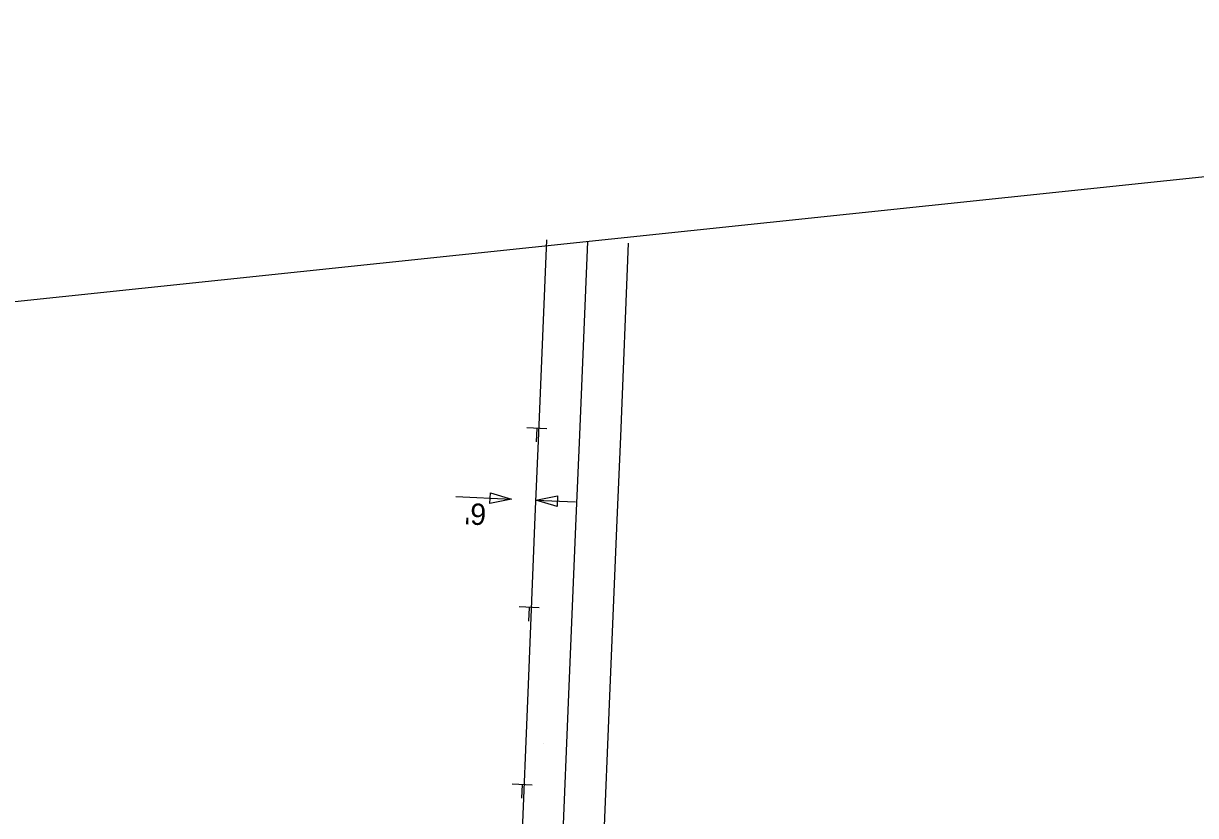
# Model space of a CAD drawing. Extents: x 633427 to 634998, y 288285 to 294065.
# Drawn here: x 634090.7 to 634419.6, y 289761.5 to 289983.8 of the extents above; entities that cross this region are included whole.
import ezdxf

# ---------------------------------------------------------------- set-up
doc = ezdxf.new("R2010")
doc.units = 0
for name, color, linetype in [('59', 7, 'Continuous'), ('Default', 7, 'Continuous'), ('R_Vert Alg Annot', 7, 'Continuous'), ('S_BASELINE', 7, 'Continuous'), ('S_SECONDARY_CTL', 7, 'Continuous'), ('S_WATER_UTILITIES', 7, 'Continuous')]:
    doc.layers.add(name, color=color, linetype=linetype)

msp = doc.modelspace()

# ---------------------------------------------------------------- linework, layer by layer
at = {"layer": '59'}
for p, q in [((634231.96, 289870.43), (634237.58, 289870.16)), ((634234.75, 289870.21), (634234.57, 289866.38)), ((634229.82, 289820.14), (634235.44, 289819.87)), ((634232.61, 289819.92), (634232.43, 289816.09)), ((634227.88, 289770.39), (634233.5, 289770.12)), ((634230.67, 289770.18), (634230.49, 289766.34))]:
    msp.add_line(p, q, dxfattribs=at)
at = {"layer": 'Default'}
for p, q in [((634212.04, 289851.04), (634227.69, 289850.33)), ((634234.55, 289850.03), (634245.63, 289849.53))]:
    msp.add_line(p, q, dxfattribs=at)
at = {"layer": 'R_Vert Alg Annot'}
msp.add_line((634236.63, 289781.59), (634236.63, 289781.59), dxfattribs=at)
at = {"layer": 'S_BASELINE'}
msp.add_lwpolyline([(634998.31, 288392.03), (633976.91, 288284.67), (633842.35, 289564.97), (633891.2, 289570.11), (633858.46, 289881.59), (634831, 289983.81)], close=True, dxfattribs=at)
at = {"layer": 'S_SECONDARY_CTL'}
for points in [[(634221.76, 289852.1), (634227.69, 289850.33), (634221.63, 289849.1)], [(634240.47, 289848.26), (634234.55, 289850.03), (634240.61, 289851.26)]]:
    msp.add_lwpolyline(points, close=True, dxfattribs=at)
at = {"layer": 'S_WATER_UTILITIES'}
for points in [[(634391.43, 288835.54), (634299.68, 289105.67), (634287, 289143.77), (634268.87, 289201.35), (634256.17, 289247.97), (634250.94, 289271.34), (634245.72, 289294.71), (634243.46, 289307.36), (634241.21, 289320), (634236.7, 289345.3), (634232.84, 289377.82), (634227.32, 289434.84), (634224.79, 289480.07), (634223.78, 289525.15), (634224.08, 289570.66), (634225.94, 289632.66), (634227.62, 289680.27), (634230.44, 289750.4), (634232.4, 289798.28), (634234.34, 289845.36), (634235.37, 289868.82), (634237.56, 289923.11)], [(634402.32, 288839.23), (634310.58, 289109.34), (634297.94, 289147.31), (634279.91, 289204.59), (634267.34, 289250.73), (634262.17, 289273.85), (634256.99, 289296.97), (634254.79, 289309.37), (634252.53, 289322.02), (634248.08, 289346.99), (634244.28, 289379.05), (634238.79, 289435.72), (634236.28, 289480.52), (634235.28, 289525.24), (634235.58, 289570.45), (634237.43, 289632.28), (634239.11, 289679.83), (634241.93, 289749.93), (634243.89, 289797.81), (634245.83, 289844.87), (634246.86, 289868.34), (634249.05, 289922.64)], [(634413.21, 288842.93), (634321.48, 289113), (634308.88, 289150.85), (634290.95, 289207.83), (634278.5, 289253.5), (634273.39, 289276.36), (634268.27, 289299.24), (634266.11, 289311.39), (634263.85, 289324.04), (634259.46, 289348.67), (634255.71, 289380.29), (634250.26, 289436.59), (634247.78, 289480.97), (634246.79, 289525.33), (634247.08, 289570.24), (634248.92, 289631.91), (634250.6, 289679.4), (634253.42, 289749.47), (634255.38, 289797.34), (634257.32, 289844.38), (634258.35, 289867.86), (634260.54, 289922.18)]]:
    msp.add_lwpolyline(points, dxfattribs=at)

# ---------------------------------------------------------------- texts
at = {"layer": 'Default'}
msp.add_text("6'", height=6, rotation=177.4332, dxfattribs=at).set_placement((634220.71, 289848.95))

doc.saveas('drawing.dxf')
